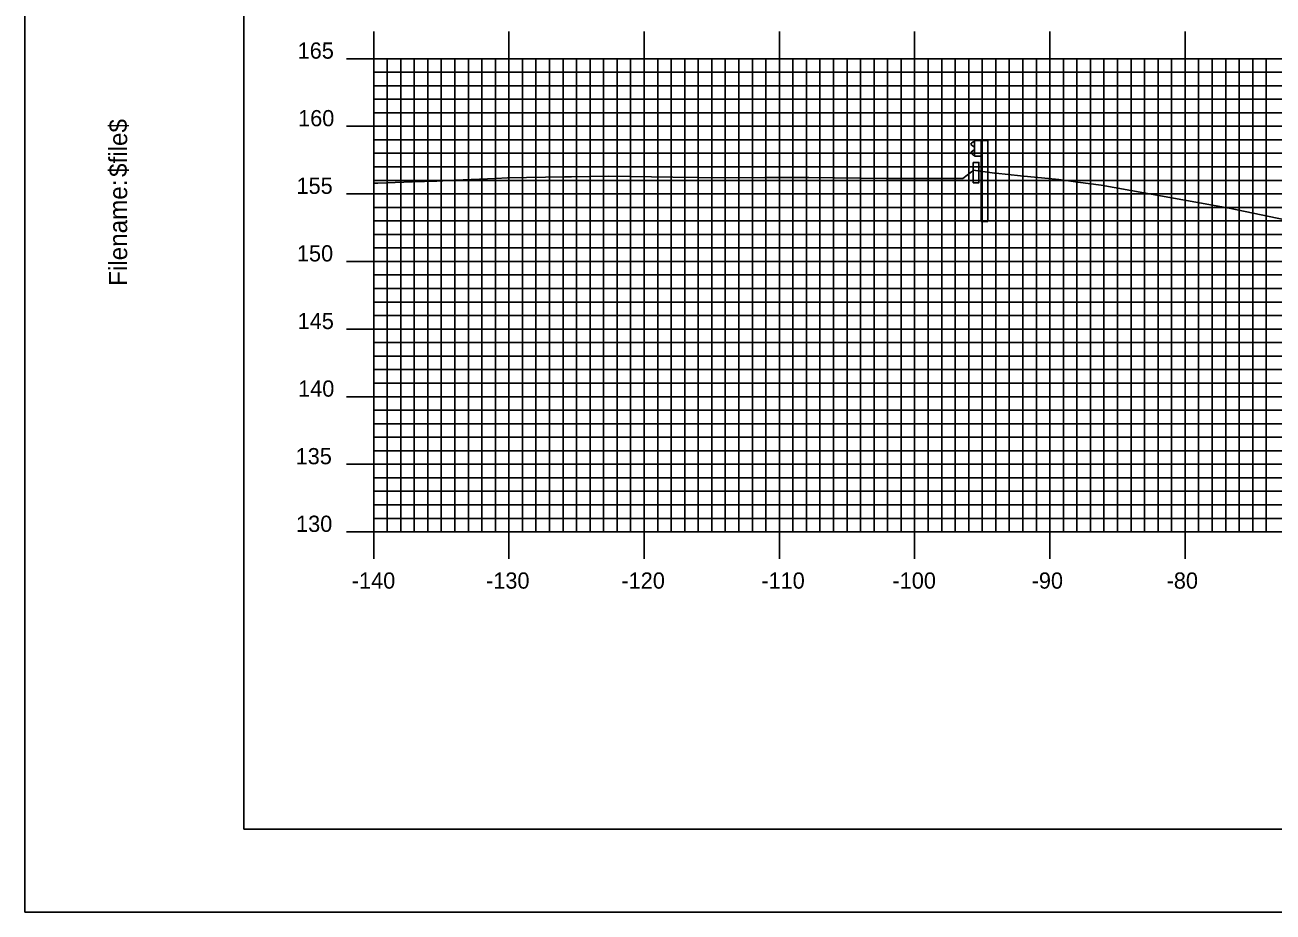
# Model space of a CAD drawing. Extents: x 850966 to 851310, y 364661 to 364881.
# Drawn here: x 850966.4 to 851058.7, y 364661.3 to 364726.9 of the extents above; entities that cross this region are included whole.
import ezdxf

# ---------------------------------------------------------------- set-up
doc = ezdxf.new("R2010")
doc.units = 0
for name, color, linetype in [('BORDER', 7, 'Continuous'), ('H_V ANNOTATION', 7, 'Continuous'), ('M_Roadway_Centerline', 7, 'Continuous'), ('MAJOR', 7, 'Continuous'), ('MINOR', 7, 'Continuous'), ('PLOT BOUNDARY', 7, 'Continuous'), ('S_Curb_Type_1', 7, 'Continuous'), ('S_Guardrail_Beam', 7, 'Continuous'), ('S_Roadway_Centerline', 7, 'Continuous')]:
    doc.layers.add(name, color=color, linetype=linetype)

msp = doc.modelspace()

# ---------------------------------------------------------------- linework, layer by layer
at = {"layer": 'BORDER'}
msp.add_lwpolyline([(850982.616, 364667.37), (851302.616, 364667.37), (851302.616, 364877.37), (850982.616, 364877.37)], close=True, dxfattribs=at)
at = {"layer": 'MAJOR'}
for p, q in [((850992.216, 364726.374), (850992.216, 364724.37)), ((851002.216, 364726.374), (851002.216, 364724.37)), ((851012.216, 364726.374), (851012.216, 364724.37)), ((851022.216, 364726.374), (851022.216, 364724.37)), ((851032.216, 364726.374), (851032.216, 364724.37)), ((851042.216, 364726.374), (851042.216, 364724.37)), ((851052.216, 364726.374), (851052.216, 364724.37)), ((850990.212, 364724.37), (850992.216, 364724.37)), ((850992.216, 364724.37), (851272.216, 364724.37)), ((850992.216, 364689.37), (850992.216, 364724.37)), ((850992.216, 364689.37), (850992.216, 364724.37)), ((850992.216, 364724.37), (851272.216, 364724.37)), ((851002.216, 364689.37), (851002.216, 364724.37)), ((851012.216, 364689.37), (851012.216, 364724.37)), ((851022.216, 364689.37), (851022.216, 364724.37)), ((851032.216, 364689.37), (851032.216, 364724.37)), ((851042.216, 364689.37), (851042.216, 364724.37)), ((851052.216, 364689.37), (851052.216, 364724.37)), ((850990.212, 364719.37), (850992.216, 364719.37)), ((850992.216, 364719.37), (851272.216, 364719.37)), ((850990.212, 364714.37), (850992.216, 364714.37)), ((850992.216, 364714.37), (851272.216, 364714.37)), ((850990.212, 364709.37), (850992.216, 364709.37)), ((850992.216, 364709.37), (851272.216, 364709.37)), ((850990.212, 364704.37), (850992.216, 364704.37)), ((850992.216, 364704.37), (851272.216, 364704.37)), ((850990.212, 364699.37), (850992.216, 364699.37)), ((850992.216, 364699.37), (851272.216, 364699.37)), ((850990.212, 364694.37), (850992.216, 364694.37)), ((850992.216, 364694.37), (851272.216, 364694.37)), ((850990.212, 364689.37), (850992.216, 364689.37)), ((850992.216, 364689.37), (851272.216, 364689.37)), ((850992.216, 364689.37), (851272.216, 364689.37)), ((850992.216, 364687.366), (850992.216, 364689.37)), ((851002.216, 364687.366), (851002.216, 364689.37)), ((851012.216, 364687.366), (851012.216, 364689.37)), ((851022.216, 364687.366), (851022.216, 364689.37)), ((851032.216, 364687.366), (851032.216, 364689.37)), ((851042.216, 364687.366), (851042.216, 364689.37)), ((851052.216, 364687.366), (851052.216, 364689.37))]:
    msp.add_line(p, q, dxfattribs=at)
at = {"layer": 'MINOR'}
for p, q in [((850993.216, 364689.37), (850993.216, 364724.37)), ((850994.216, 364689.37), (850994.216, 364724.37)), ((850995.216, 364689.37), (850995.216, 364724.37)), ((850996.216, 364689.37), (850996.216, 364724.37)), ((850997.216, 364689.37), (850997.216, 364724.37)), ((850998.216, 364689.37), (850998.216, 364724.37)), ((850999.216, 364689.37), (850999.216, 364724.37)), ((851000.216, 364689.37), (851000.216, 364724.37)), ((851001.216, 364689.37), (851001.216, 364724.37)), ((851003.216, 364689.37), (851003.216, 364724.37)), ((851004.216, 364689.37), (851004.216, 364724.37)), ((851005.216, 364689.37), (851005.216, 364724.37)), ((851006.216, 364689.37), (851006.216, 364724.37)), ((851007.216, 364689.37), (851007.216, 364724.37)), ((851008.216, 364689.37), (851008.216, 364724.37)), ((851009.216, 364689.37), (851009.216, 364724.37)), ((851010.216, 364689.37), (851010.216, 364724.37)), ((851011.216, 364689.37), (851011.216, 364724.37)), ((851013.216, 364689.37), (851013.216, 364724.37)), ((851014.216, 364689.37), (851014.216, 364724.37)), ((851015.216, 364689.37), (851015.216, 364724.37)), ((851016.216, 364689.37), (851016.216, 364724.37)), ((851017.216, 364689.37), (851017.216, 364724.37)), ((851018.216, 364689.37), (851018.216, 364724.37)), ((851019.216, 364689.37), (851019.216, 364724.37)), ((851020.216, 364689.37), (851020.216, 364724.37)), ((851021.216, 364689.37), (851021.216, 364724.37)), ((851023.216, 364689.37), (851023.216, 364724.37)), ((851024.216, 364689.37), (851024.216, 364724.37)), ((851025.216, 364689.37), (851025.216, 364724.37)), ((851026.216, 364689.37), (851026.216, 364724.37)), ((851027.216, 364689.37), (851027.216, 364724.37)), ((851028.216, 364689.37), (851028.216, 364724.37)), ((851029.216, 364689.37), (851029.216, 364724.37)), ((851030.216, 364689.37), (851030.216, 364724.37)), ((851031.216, 364689.37), (851031.216, 364724.37)), ((851033.216, 364689.37), (851033.216, 364724.37)), ((851034.216, 364689.37), (851034.216, 364724.37)), ((851035.216, 364689.37), (851035.216, 364724.37)), ((851036.216, 364689.37), (851036.216, 364724.37)), ((851037.216, 364689.37), (851037.216, 364724.37)), ((851038.216, 364689.37), (851038.216, 364724.37)), ((851039.216, 364689.37), (851039.216, 364724.37)), ((851040.216, 364689.37), (851040.216, 364724.37)), ((851041.216, 364689.37), (851041.216, 364724.37)), ((851043.216, 364689.37), (851043.216, 364724.37)), ((851044.216, 364689.37), (851044.216, 364724.37)), ((851045.216, 364689.37), (851045.216, 364724.37)), ((851046.216, 364689.37), (851046.216, 364724.37)), ((851047.216, 364689.37), (851047.216, 364724.37)), ((851048.216, 364689.37), (851048.216, 364724.37)), ((851049.216, 364689.37), (851049.216, 364724.37)), ((851050.216, 364689.37), (851050.216, 364724.37)), ((851051.216, 364689.37), (851051.216, 364724.37)), ((851053.216, 364689.37), (851053.216, 364724.37)), ((851054.216, 364689.37), (851054.216, 364724.37)), ((851055.216, 364689.37), (851055.216, 364724.37)), ((851056.216, 364689.37), (851056.216, 364724.37)), ((851057.216, 364689.37), (851057.216, 364724.37)), ((851058.216, 364689.37), (851058.216, 364724.37)), ((850992.216, 364723.37), (851272.216, 364723.37)), ((850992.216, 364723.37), (850994.22, 364723.37)), ((850992.216, 364722.37), (851272.216, 364722.37)), ((850992.216, 364722.37), (850994.22, 364722.37)), ((850992.216, 364721.37), (851272.216, 364721.37)), ((850992.216, 364721.37), (850994.22, 364721.37)), ((850992.216, 364720.37), (851272.216, 364720.37)), ((850992.216, 364720.37), (850994.22, 364720.37)), ((850992.216, 364718.37), (851272.216, 364718.37)), ((850992.216, 364718.37), (850994.22, 364718.37)), ((850992.216, 364717.37), (851272.216, 364717.37)), ((850992.216, 364717.37), (850994.22, 364717.37)), ((850992.216, 364716.37), (851272.216, 364716.37)), ((850992.216, 364716.37), (850994.22, 364716.37)), ((850992.216, 364715.37), (851272.216, 364715.37)), ((850992.216, 364715.37), (850994.22, 364715.37)), ((850992.216, 364713.37), (851272.216, 364713.37)), ((850992.216, 364713.37), (850994.22, 364713.37)), ((850992.216, 364712.37), (851272.216, 364712.37)), ((850992.216, 364712.37), (850994.22, 364712.37)), ((850992.216, 364711.37), (851272.216, 364711.37)), ((850992.216, 364711.37), (850994.22, 364711.37)), ((850992.216, 364710.37), (851272.216, 364710.37)), ((850992.216, 364710.37), (850994.22, 364710.37)), ((850992.216, 364708.37), (851272.216, 364708.37)), ((850992.216, 364708.37), (850994.22, 364708.37)), ((850992.216, 364707.37), (851272.216, 364707.37)), ((850992.216, 364707.37), (850994.22, 364707.37)), ((850992.216, 364706.37), (851272.216, 364706.37)), ((850992.216, 364706.37), (850994.22, 364706.37)), ((850992.216, 364705.37), (851272.216, 364705.37)), ((850992.216, 364705.37), (850994.22, 364705.37)), ((850992.216, 364703.37), (851272.216, 364703.37)), ((850992.216, 364703.37), (850994.22, 364703.37)), ((850992.216, 364702.37), (851272.216, 364702.37)), ((850992.216, 364702.37), (850994.22, 364702.37)), ((850992.216, 364701.37), (851272.216, 364701.37)), ((850992.216, 364701.37), (850994.22, 364701.37)), ((850992.216, 364700.37), (851272.216, 364700.37)), ((850992.216, 364700.37), (850994.22, 364700.37)), ((850992.216, 364698.37), (851272.216, 364698.37)), ((850992.216, 364698.37), (850994.22, 364698.37)), ((850992.216, 364697.37), (851272.216, 364697.37)), ((850992.216, 364697.37), (850994.22, 364697.37)), ((850992.216, 364696.37), (851272.216, 364696.37)), ((850992.216, 364696.37), (850994.22, 364696.37)), ((850992.216, 364695.37), (851272.216, 364695.37)), ((850992.216, 364695.37), (850994.22, 364695.37)), ((850992.216, 364693.37), (851272.216, 364693.37)), ((850992.216, 364693.37), (850994.22, 364693.37)), ((850992.216, 364692.37), (851272.216, 364692.37)), ((850992.216, 364692.37), (850994.22, 364692.37)), ((850992.216, 364691.37), (851272.216, 364691.37)), ((850992.216, 364691.37), (850994.22, 364691.37)), ((850992.216, 364690.37), (851272.216, 364690.37)), ((850992.216, 364690.37), (850994.22, 364690.37))]:
    msp.add_line(p, q, dxfattribs=at)
at = {"layer": 'PLOT BOUNDARY'}
msp.add_lwpolyline([(850966.429, 364661.252), (851306.429, 364661.252), (851306.429, 364881.252), (850966.429, 364881.252)], close=True, dxfattribs=at)
at = {"layer": 'S_Curb_Type_1'}
msp.add_lwpolyline([(851036.547, 364716.695), (851036.964, 364716.695), (851036.964, 364715.195), (851036.547, 364715.195)], close=True, dxfattribs=at)
msp.add_lwpolyline([(851036.547, 364716.695), (851036.964, 364716.695), (851036.964, 364715.195), (851036.547, 364715.195)], close=True, dxfattribs=at)
at = {"layer": 'S_Guardrail_Beam'}
for p, q in [((851036.553, 364718.222), (851036.41, 364718.122)), ((851036.553, 364718.222), (851036.41, 364718.122)), ((851036.41, 364717.979), (851036.605, 364717.843)), ((851036.41, 364717.979), (851036.605, 364717.843)), ((851036.652, 364718.243), (851036.57, 364718.229)), ((851036.652, 364718.243), (851036.57, 364718.229)), ((851036.652, 364718.316), (851037.142, 364718.316)), ((851036.652, 364717.149), (851036.652, 364718.316)), ((851036.652, 364718.316), (851037.142, 364718.316)), ((851036.652, 364717.149), (851036.652, 364718.316)), ((851037.142, 364718.316), (851037.633, 364718.316)), ((851037.142, 364718.316), (851037.142, 364717.149)), ((851037.142, 364718.316), (851037.633, 364718.316)), ((851037.142, 364718.316), (851037.142, 364717.149)), ((851037.633, 364718.316), (851037.633, 364712.316)), ((851037.633, 364718.316), (851037.633, 364712.316)), ((851036.605, 364717.623), (851036.41, 364717.487)), ((851036.605, 364717.623), (851036.41, 364717.487)), ((851036.41, 364717.344), (851036.553, 364717.244)), ((851036.41, 364717.344), (851036.553, 364717.244)), ((851036.57, 364717.237), (851036.652, 364717.222)), ((851036.57, 364717.237), (851036.652, 364717.222)), ((851036.639, 364717.778), (851036.639, 364717.687)), ((851036.639, 364717.778), (851036.639, 364717.687)), ((851037.142, 364717.149), (851036.652, 364717.149)), ((851037.142, 364717.149), (851036.652, 364717.149)), ((851037.142, 364712.316), (851037.142, 364717.149)), ((851037.142, 364712.316), (851037.142, 364717.149)), ((851037.142, 364712.316), (851037.633, 364712.316)), ((851037.142, 364712.316), (851037.633, 364712.316))]:
    msp.add_line(p, q, dxfattribs=at)
for centre, major_axis, start_param, end_param in [((851036.46, 364718.05), (-0.0877, 0), 5.323254, 7.243116), ((851036.46, 364718.05), (-0.0877, 0), 5.323254, 7.243116), ((851036.577, 364718.188), (-0.0417, 0), 4.886922, 5.323254), ((851036.577, 364718.188), (-0.0417, 0), 4.886922, 5.323254), ((851036.46, 364717.415), (-0.0877, 0), 5.323254, 7.243116), ((851036.46, 364717.415), (-0.0877, 0), 5.323254, 7.243116), ((851036.577, 364717.278), (-0.0417, 0), 0.959931, 1.396263), ((851036.577, 364717.278), (-0.0417, 0), 0.959931, 1.396263), ((851036.56, 364717.778), (0.0789, 0), 0, 0.959931), ((851036.56, 364717.778), (0.0789, 0), 0, 0.959931), ((851036.56, 364717.687), (0.0789, 0), 5.323254, 6.283185), ((851036.56, 364717.687), (0.0789, 0), 5.323254, 6.283185)]:
    msp.add_ellipse(centre, major_axis=major_axis, ratio=0.995501, start_param=start_param, end_param=end_param, dxfattribs=at)
at = {"layer": 'S_Roadway_Centerline'}
msp.add_lwpolyline([(850992.216, 364715.15), (850992.516, 364715.159), (850995.092, 364715.267), (850996.889, 364715.321), (850998.223, 364715.374), (851001.25, 364715.498), (851002.101, 364715.557), (851006.316, 364715.622), (851006.846, 364715.63), (851009.573, 364715.681), (851014.323, 364715.607), (851018.145, 364715.565), (851021.144, 364715.589), (851024.023, 364715.588), (851024.394, 364715.577), (851030.114, 364715.495), (851032.166, 364715.519), (851035.529, 364715.495), (851035.788, 364715.511), (851036.42, 364716.008), (851036.547, 364716.112), (851038.124, 364715.911), (851038.158, 364715.906), (851038.224, 364715.897), (851040.045, 364715.7), (851042.876, 364715.425), (851044.271, 364715.238), (851045.995, 364715.024), (851055.476, 364713.312), (851063.754, 364711.589)], dxfattribs=at)

# ---------------------------------------------------------------- texts
at = {"layer": 'BORDER'}
for s, p in [('$file$', (850973.986, 364715.621)), ('Filename:', (850973.986, 364707.567))]:
    msp.add_text(s, height=1.3392, rotation=90, dxfattribs=at).set_placement(p)
at = {"layer": 'H_V ANNOTATION'}
for s, p in [('165', (850986.593, 364724.37)), ('160', (850986.626, 364719.37)), ('155', (850986.508, 364714.37)), ('150', (850986.54, 364709.37)), ('145', (850986.593, 364704.37)), ('140', (850986.626, 364699.37)), ('135', (850986.444, 364694.37)), ('130', (850986.476, 364689.37)), ('-140', (850990.6, 364685.17)), ('-130', (851000.525, 364685.17)), ('-120', (851010.535, 364685.17)), ('-110', (851020.878, 364685.17)), ('-100', (851030.578, 364685.17)), ('-90', (851040.867, 364685.17)), ('-80', (851050.846, 364685.17))]:
    msp.add_text(s, height=1.2, dxfattribs=at).set_placement(p)
at = {"layer": 'M_Roadway_Centerline'}
for s, p in [('C', (851002.096, 364715.557)), ('L', (851002.101, 364715.55))]:
    msp.add_text(s, height=0.0146, dxfattribs=at).set_placement(p)
at = {"layer": 'MAJOR'}
msp.add_text('-', height=0.012, dxfattribs=at).set_placement((850992.207, 364689.37))

doc.saveas('drawing.dxf')
